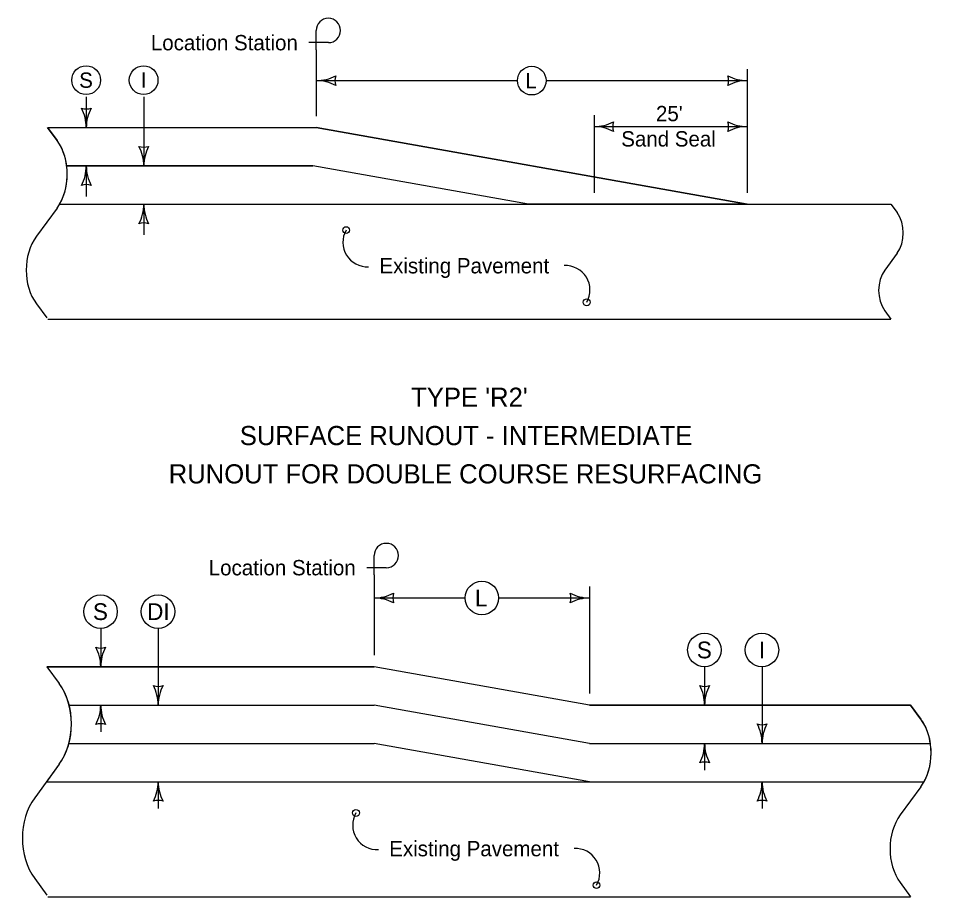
# Model space of a CAD drawing. Extents: x 10133 to 81668, y 2218 to 11018.
# Drawn here: x 20281 to 21238, y 3162 to 4079 of the extents above; entities that cross this region are included whole.
import ezdxf

# ---------------------------------------------------------------- set-up
doc = ezdxf.new("R2010")
doc.units = 0
for name, color, linetype in [('dsnNonPlotable', 7, 'Continuous'), ('dsnStdBlock', 7, 'Continuous'), ('dsnStdBlockNotModified', 7, 'Continuous'), ('dsnStdShading', 7, 'Continuous')]:
    doc.layers.add(name, color=color, linetype=linetype)

msp = doc.modelspace()

# ---------------------------------------------------------------- linework, layer by layer
at = {"layer": 'dsnNonPlotable'}
for p, q in [((20652.45, 3402.05), (20310.91, 3402.05)), ((20310.91, 3402.05), (20323.71, 3384.58)), ((20652.45, 3402.05), (20310.91, 3402.05)), ((20310.91, 3402.05), (20323.71, 3384.58)), ((20877.45, 3362.05), (20652.45, 3402.05)), ((20877.45, 3362.05), (20652.45, 3402.05)), ((21212.45, 3362.05), (20877.45, 3362.05)), ((21212.45, 3362.05), (20877.45, 3362.05)), ((21222.87, 3347.82), (21212.45, 3362.05)), ((21222.87, 3347.82), (21212.45, 3362.05)), ((20323.71, 3300.26), (20310.37, 3282.05)), ((20323.71, 3300.26), (20310.37, 3282.05)), ((20310.37, 3282.05), (20877.45, 3282.05)), ((20310.37, 3282.05), (20877.45, 3282.05)), ((20877.45, 3282.05), (21226.58, 3282.05)), ((20877.45, 3282.05), (21226.58, 3282.05))]:
    msp.add_line(p, q, dxfattribs=at)
for centre, major_axis, ratio, start_param, end_param in [((20292.82, 3342.42), (0, -59.62), 0.732667, 0.785328, 2.356194), ((20292.82, 3342.42), (0, -59.62), 0.732667, 0.785328, 2.356194), ((21197.28, 3312.05), (0, -50), 0.73263, 0.927302, 2.368135), ((21197.28, 3312.05), (0, -50), 0.73263, 0.927302, 2.368135)]:
    msp.add_ellipse(centre, major_axis=major_axis, ratio=ratio, start_param=start_param, end_param=end_param, dxfattribs=at)
at = {"layer": 'dsnStdBlock'}
for p, q in [((20592.01, 4045.8), (20592.01, 4066.12)), ((20592.01, 4045.8), (20592.01, 4066.12)), ((20604.71, 4053.42), (20584.39, 4053.42)), ((20604.71, 4053.42), (20584.39, 4053.42)), ((20592.01, 4045.8), (20592.01, 3976.8)), ((20592.01, 4045.8), (20592.01, 3976.8)), ((21042.01, 4025.8), (21042.01, 3896.8)), ((21042.01, 4025.8), (21042.01, 3896.8)), ((20592.01, 4013.8), (20802.02, 4013.8)), ((20592.01, 4013.8), (20802.02, 4013.8)), ((20832.02, 4013.8), (21042.01, 4013.8)), ((20832.02, 4013.8), (21042.01, 4013.8)), ((20352.01, 3996.8), (20352.01, 3964.8)), ((20352.01, 3996.8), (20352.01, 3964.8)), ((20412.01, 3996.8), (20412.01, 3924.8)), ((20412.01, 3996.8), (20412.01, 3924.8)), ((20882.01, 3977.8), (20882.01, 3896.8)), ((20882.01, 3977.8), (20882.01, 3896.8)), ((20311.65, 3964.8), (20321.45, 3951.42)), ((20311.65, 3964.8), (20321.45, 3951.42)), ((20312.01, 3964.8), (20592.01, 3964.8)), ((20312.01, 3964.8), (20592.01, 3964.8)), ((21042.01, 3884.8), (20592.01, 3964.8)), ((21042.01, 3884.8), (20592.01, 3964.8)), ((20882.01, 3965.8), (21042.01, 3965.8)), ((20882.01, 3965.8), (21042.01, 3965.8)), ((20331.62, 3924.8), (20588.49, 3924.8)), ((20331.62, 3924.8), (20588.49, 3924.8)), ((20352.01, 3924.8), (20352.01, 3892.8)), ((20352.01, 3924.8), (20352.01, 3892.8)), ((20813.49, 3884.8), (20588.49, 3924.8)), ((20813.49, 3884.8), (20588.49, 3924.8)), ((20324.46, 3884.8), (20813.49, 3884.8)), ((20324.46, 3884.8), (20813.49, 3884.8)), ((20412.01, 3884.8), (20412.01, 3852.8)), ((20412.01, 3884.8), (20412.01, 3852.8)), ((20813.49, 3884.8), (21042.01, 3884.8)), ((20813.49, 3884.8), (21042.01, 3884.8)), ((21042.01, 3884.8), (21192.01, 3884.8)), ((21042.01, 3884.8), (21192.01, 3884.8)), ((21192.01, 3884.8), (21198.45, 3876.02)), ((21192.01, 3884.8), (21198.45, 3876.02)), ((20321.45, 3880.7), (20300, 3851.42)), ((20321.45, 3880.7), (20300, 3851.42)), ((21198.45, 3833.59), (21185.58, 3816.02)), ((21198.45, 3833.59), (21185.58, 3816.02)), ((20300, 3780.7), (20310.73, 3766.06)), ((20300, 3780.7), (20310.73, 3766.06)), ((21185.58, 3773.59), (21192.01, 3764.8)), ((21185.58, 3773.59), (21192.01, 3764.8)), ((20312.01, 3764.8), (21192.01, 3764.8)), ((20312.01, 3764.8), (21192.01, 3764.8)), ((20652.45, 3497.81), (20652.45, 3518.13)), ((20652.45, 3497.81), (20652.45, 3518.13)), ((20665.15, 3505.43), (20644.83, 3505.43)), ((20665.15, 3505.43), (20644.83, 3505.43)), ((20652.45, 3497.81), (20652.45, 3414.05)), ((20652.45, 3497.81), (20652.45, 3414.05)), ((20877.45, 3485.81), (20877.45, 3374.05)), ((20877.45, 3485.81), (20877.45, 3374.05)), ((20652.45, 3473.81), (20747.45, 3473.81)), ((20652.45, 3473.81), (20747.45, 3473.81)), ((20782.45, 3473.81), (20877.45, 3473.81)), ((20782.45, 3473.81), (20877.45, 3473.81)), ((20367.08, 3442.05), (20367.08, 3402.05)), ((20367.08, 3442.05), (20367.08, 3402.05)), ((20427.08, 3442.05), (20427.08, 3362.05)), ((20427.08, 3442.05), (20427.08, 3362.05)), ((20310.91, 3402.05), (20652.45, 3402.05)), ((20310.91, 3402.05), (20652.45, 3402.05)), ((20310.91, 3402.04), (20323.71, 3384.59)), ((20310.91, 3402.04), (20323.71, 3384.59)), ((20877.45, 3362.05), (20652.45, 3402.05)), ((20877.45, 3362.05), (20652.45, 3402.05)), ((20997.45, 3402.05), (20997.45, 3362.05)), ((20997.45, 3402.05), (20997.45, 3362.05)), ((21057.45, 3402.05), (21057.45, 3322.05)), ((21057.45, 3402.05), (21057.45, 3322.05)), ((20334.07, 3362.05), (20652.45, 3362.05)), ((20334.07, 3362.05), (20652.45, 3362.05)), ((20367.08, 3362.05), (20367.08, 3334.05)), ((20367.08, 3362.05), (20367.08, 3334.05)), ((20877.45, 3322.05), (20652.45, 3362.05)), ((20877.45, 3322.05), (20652.45, 3362.05)), ((20877.45, 3362.05), (21212.45, 3362.05)), ((20877.45, 3362.05), (21212.45, 3362.05)), ((21212.45, 3362.05), (21223.17, 3347.4)), ((21212.45, 3362.05), (21223.17, 3347.4)), ((20333.88, 3322.05), (20652.45, 3322.05)), ((20333.88, 3322.05), (20652.45, 3322.05)), ((20877.45, 3282.05), (20652.45, 3322.05)), ((20877.45, 3282.05), (20652.45, 3322.05)), ((20877.45, 3322.05), (21233.17, 3322.05)), ((20877.45, 3322.05), (21233.17, 3322.05)), ((20997.45, 3322.05), (20997.45, 3294.05)), ((20997.45, 3322.05), (20997.45, 3294.05)), ((20323.71, 3300.26), (20298.13, 3265.34)), ((20323.71, 3300.26), (20298.13, 3265.34)), ((20310.37, 3282.05), (20877.45, 3282.05)), ((20310.37, 3282.05), (20877.45, 3282.05)), ((20427.08, 3282.05), (20427.08, 3254.05)), ((20427.08, 3282.05), (20427.08, 3254.05)), ((20877.45, 3282.05), (21226.58, 3282.05)), ((20877.45, 3282.05), (21226.58, 3282.05)), ((21057.45, 3282.05), (21057.45, 3254.05)), ((21057.45, 3282.05), (21057.45, 3254.05)), ((21223.17, 3276.69), (21201.73, 3247.4)), ((21223.17, 3276.69), (21201.73, 3247.4)), ((20298.13, 3181.01), (20310.91, 3163.55)), ((20298.13, 3181.01), (20310.91, 3163.55)), ((21201.73, 3176.69), (21212.45, 3162.05)), ((21201.73, 3176.69), (21212.45, 3162.05)), ((20312.01, 3162.05), (21212.45, 3162.05)), ((20312.01, 3162.05), (21212.45, 3162.05))]:
    msp.add_line(p, q, dxfattribs=at)
for centre, radius in [((20351.83, 4014.3), 15), ((20351.83, 4014.3), 15), ((20411.83, 4014.3), 15), ((20411.83, 4014.3), 15), ((20817.02, 4013.8), 15), ((20817.02, 4013.8), 15), ((20623.27, 3857.8), 3.56), ((20623.27, 3857.8), 3.56), ((20874.4, 3782.44), 3.56), ((20874.4, 3782.44), 3.56), ((20764.95, 3473.81), 17.5), ((20764.95, 3473.81), 17.5), ((20366.9, 3459.55), 17.5), ((20366.9, 3459.55), 17.5), ((20426.9, 3459.55), 17.5), ((20426.9, 3459.55), 17.5), ((20997.27, 3419.55), 17.5), ((20997.27, 3419.55), 17.5), ((21057.27, 3419.55), 17.5), ((21057.27, 3419.55), 17.5), ((20633.49, 3249.41), 3.56), ((20633.49, 3249.41), 3.56), ((20884.62, 3174.05), 3.56), ((20884.62, 3174.05), 3.56)]:
    msp.add_circle(centre, radius, dxfattribs=at)
for centre, radius, start, end in [((20604.71, 4066.12), 12.7, 270, 180), ((20604.71, 4066.12), 12.7, 270, 180), ((20592.01, 4056.98), 43.18, 270, 298.07249), ((20592.01, 4056.98), 43.18, 270, 298.07249), ((20628.22, 4013.8), 16.68, 162.26665, 197.73335), ((20628.22, 4013.8), 16.68, 162.26665, 197.73335), ((21005.81, 4013.8), 16.68, 342.26665, 17.73335), ((21042.01, 4056.98), 43.18, 241.92751, 270), ((21005.81, 4013.8), 16.68, 342.26665, 17.73335), ((21042.01, 4056.98), 43.18, 241.92751, 270), ((20592.01, 3970.62), 43.18, 61.92751, 90), ((20592.01, 3970.62), 43.18, 61.92751, 90), ((21042.01, 3970.62), 43.18, 90, 118.07249), ((21042.01, 3970.62), 43.18, 90, 118.07249), ((20352.01, 4001.01), 16.68, 252.26665, 287.73335), ((20308.83, 3964.8), 43.18, 360, 28.07249), ((20352.01, 4001.01), 16.68, 252.26665, 287.73335), ((20308.83, 3964.8), 43.18, 360, 28.07249), ((20395.19, 3964.8), 43.18, 151.92751, 180), ((20395.19, 3964.8), 43.18, 151.92751, 180), ((20882.01, 4008.98), 43.18, 270, 298.07249), ((20882.01, 4008.98), 43.18, 270, 298.07249), ((20918.22, 3965.8), 16.68, 162.26665, 197.73335), ((20918.22, 3965.8), 16.68, 162.26665, 197.73335), ((21005.81, 3965.8), 16.68, 342.26665, 17.73335), ((21042.01, 4008.98), 43.18, 241.92751, 270), ((21005.81, 3965.8), 16.68, 342.26665, 17.73335), ((21042.01, 4008.98), 43.18, 241.92751, 270), ((20882.01, 3922.62), 43.18, 61.92751, 90), ((20882.01, 3922.62), 43.18, 61.92751, 90), ((21042.01, 3922.62), 43.18, 90, 118.07249), ((21042.01, 3922.62), 43.18, 90, 118.07249), ((20412.01, 3961.01), 16.68, 252.26665, 287.73335), ((20368.83, 3924.8), 43.18, 360, 28.07249), ((20412.01, 3961.01), 16.68, 252.26665, 287.73335), ((20368.83, 3924.8), 43.18, 360, 28.07249), ((20412.01, 3961.01), 16.68, 252.26665, 287.73335), ((20368.83, 3924.8), 43.18, 360, 28.07249), ((20412.01, 3961.01), 16.68, 252.26665, 287.73335), ((20368.83, 3924.8), 43.18, 360, 28.07249), ((20455.19, 3924.8), 43.18, 151.92751, 180), ((20455.19, 3924.8), 43.18, 151.92751, 180), ((20455.19, 3924.8), 43.18, 151.92751, 180), ((20455.19, 3924.8), 43.18, 151.92751, 180), ((20308.83, 3924.8), 43.18, 331.92751, 360), ((20308.83, 3924.8), 43.18, 331.92751, 360), ((20395.19, 3924.8), 43.18, 180, 208.07249), ((20395.19, 3924.8), 43.18, 180, 208.07249), ((20352.01, 3888.6), 16.68, 72.26665, 107.73335), ((20352.01, 3888.6), 16.68, 72.26665, 107.73335), ((20368.83, 3884.8), 43.18, 331.92751, 360), ((20368.83, 3884.8), 43.18, 331.92751, 360), ((20455.19, 3884.8), 43.18, 180, 208.07249), ((20455.19, 3884.8), 43.18, 180, 208.07249), ((20412.01, 3848.6), 16.68, 72.26665, 107.73335), ((20412.01, 3848.6), 16.68, 72.26665, 107.73335), ((20645.42, 3845.05), 25.56, 150.06834, 272.84357), ((20645.42, 3845.05), 25.56, 150.06834, 272.84357), ((20852.25, 3795.2), 25.56, 330.06834, 92.84357), ((20852.25, 3795.2), 25.56, 330.06834, 92.84357), ((20665.15, 3518.13), 12.7, 270, 180), ((20665.15, 3518.13), 12.7, 270, 180), ((20652.45, 3516.99), 43.18, 270, 298.07249), ((20652.45, 3516.99), 43.18, 270, 298.07249), ((20652.45, 3430.63), 43.18, 61.92751, 90), ((20652.45, 3430.63), 43.18, 61.92751, 90), ((20688.66, 3473.81), 16.68, 162.26665, 197.73335), ((20688.66, 3473.81), 16.68, 162.26665, 197.73335), ((20841.24, 3473.81), 16.68, 342.26665, 17.73335), ((20877.45, 3516.99), 43.18, 241.92751, 270), ((20841.24, 3473.81), 16.68, 342.26665, 17.73335), ((20877.45, 3516.99), 43.18, 241.92751, 270), ((20877.45, 3430.63), 43.18, 90, 118.07249), ((20877.45, 3430.63), 43.18, 90, 118.07249), ((20367.08, 3438.25), 16.68, 252.26665, 287.73335), ((20323.9, 3402.05), 43.18, 360, 28.07249), ((20367.08, 3438.25), 16.68, 252.26665, 287.73335), ((20323.9, 3402.05), 43.18, 360, 28.07249), ((20410.26, 3402.05), 43.18, 151.92751, 180), ((20410.26, 3402.05), 43.18, 151.92751, 180), ((20427.08, 3398.25), 16.68, 252.26665, 287.73335), ((20383.9, 3362.05), 43.18, 360, 28.07249), ((20427.08, 3398.25), 16.68, 252.26665, 287.73335), ((20383.9, 3362.05), 43.18, 360, 28.07249), ((20470.26, 3362.05), 43.18, 151.92751, 180), ((20470.26, 3362.05), 43.18, 151.92751, 180), ((20997.45, 3398.25), 16.68, 252.26665, 287.73335), ((20954.27, 3362.05), 43.18, 360, 28.07249), ((20997.45, 3398.25), 16.68, 252.26665, 287.73335), ((20954.27, 3362.05), 43.18, 360, 28.07249), ((21040.63, 3362.05), 43.18, 151.92751, 180), ((21040.63, 3362.05), 43.18, 151.92751, 180), ((20323.9, 3362.05), 43.18, 331.92751, 360), ((20323.9, 3362.05), 43.18, 331.92751, 360), ((20410.26, 3362.05), 43.18, 180, 208.07249), ((20410.26, 3362.05), 43.18, 180, 208.07249), ((20367.08, 3325.84), 16.68, 72.26665, 107.73335), ((20367.08, 3325.84), 16.68, 72.26665, 107.73335), ((21057.45, 3358.25), 16.68, 252.26665, 287.73335), ((21014.27, 3322.05), 43.18, 360, 28.07249), ((21057.45, 3358.25), 16.68, 252.26665, 287.73335), ((21014.27, 3322.05), 43.18, 360, 28.07249), ((21100.63, 3322.05), 43.18, 151.92751, 180), ((21100.63, 3322.05), 43.18, 151.92751, 180), ((20954.27, 3322.05), 43.18, 331.92751, 360), ((20954.27, 3322.05), 43.18, 331.92751, 360), ((21040.63, 3322.05), 43.18, 180, 208.07249), ((21040.63, 3322.05), 43.18, 180, 208.07249), ((20997.45, 3285.84), 16.68, 72.26665, 107.73335), ((20997.45, 3285.84), 16.68, 72.26665, 107.73335), ((20383.9, 3282.05), 43.18, 331.92751, 360), ((20383.9, 3282.05), 43.18, 331.92751, 360), ((20470.26, 3282.05), 43.18, 180, 208.07249), ((20470.26, 3282.05), 43.18, 180, 208.07249), ((21014.27, 3282.05), 43.18, 331.92751, 360), ((21014.27, 3282.05), 43.18, 331.92751, 360), ((21100.63, 3282.05), 43.18, 180, 208.07249), ((21100.63, 3282.05), 43.18, 180, 208.07249), ((20427.08, 3245.84), 16.68, 72.26665, 107.73335), ((20427.08, 3245.84), 16.68, 72.26665, 107.73335), ((21057.45, 3245.84), 16.68, 72.26665, 107.73335), ((21057.45, 3245.84), 16.68, 72.26665, 107.73335), ((20655.64, 3236.66), 25.56, 150.06834, 272.84357), ((20655.64, 3236.66), 25.56, 150.06834, 272.84357), ((20862.47, 3186.81), 25.56, 330.06834, 92.84357), ((20862.47, 3186.81), 25.56, 330.06834, 92.84357)]:
    msp.add_arc(centre, radius, start, end, dxfattribs=at)
for centre, major_axis, ratio in [((20295.55, 3916.06), (0, -50), 0.732645), ((20295.55, 3916.06), (0, -50), 0.732645), ((21182.91, 3854.8), (0, -30), 0.732645), ((21182.91, 3854.8), (0, -30), 0.732645), ((20325.9, 3816.06), (0, 50), 0.732645), ((20325.9, 3816.06), (0, 50), 0.732645), ((21201.12, 3794.8), (0, 30), 0.732645), ((21201.12, 3794.8), (0, 30), 0.732645), ((20292.82, 3342.42), (0, -59.62), 0.732667), ((20292.82, 3342.42), (0, -59.62), 0.732667), ((21197.28, 3312.05), (0, -50), 0.73263), ((21197.28, 3312.05), (0, -50), 0.73263), ((20329.01, 3223.18), (0, 59.62), 0.732667), ((20329.01, 3223.18), (0, 59.62), 0.732667), ((21227.62, 3212.05), (0, 50), 0.73263), ((21227.62, 3212.05), (0, 50), 0.73263)]:
    msp.add_ellipse(centre, major_axis=major_axis, ratio=ratio, start_param=0.785398, end_param=2.356194, dxfattribs=at)
at = {"layer": 'dsnStdShading'}
for p, q in [((20321.45, 3951.42), (20311.65, 3964.8)), ((20321.45, 3951.42), (20311.65, 3964.8)), ((20312.01, 3964.8), (20592.01, 3964.8)), ((20312.01, 3964.8), (20592.01, 3964.8)), ((20592.01, 3964.8), (21042.01, 3884.8)), ((20592.01, 3964.8), (21042.01, 3884.8)), ((20588.49, 3924.8), (20331.62, 3924.8)), ((20588.49, 3924.8), (20331.62, 3924.8)), ((20588.49, 3924.8), (20331.62, 3924.8)), ((20588.49, 3924.8), (20331.62, 3924.8)), ((20813.49, 3884.8), (20588.49, 3924.8)), ((20813.49, 3884.8), (20588.49, 3924.8)), ((20813.49, 3884.8), (20588.49, 3924.8)), ((20813.49, 3884.8), (20588.49, 3924.8)), ((20324.14, 3884.8), (20813.49, 3884.8)), ((20324.14, 3884.8), (20813.49, 3884.8)), ((21042.01, 3884.8), (20813.49, 3884.8)), ((21042.01, 3884.8), (20813.49, 3884.8))]:
    msp.add_line(p, q, dxfattribs=at)
for start_param, end_param in [(1.746484, 2.356194), (1.746484, 2.356194), (0.89539, 1.746484), (0.89539, 1.746484)]:
    msp.add_ellipse((20295.55, 3916.06), major_axis=(0, -50), ratio=0.732645, start_param=start_param, end_param=end_param, dxfattribs=at)

# ---------------------------------------------------------------- texts
at = {"layer": 'dsnStdBlockNotModified'}
for s, height, p in [('Location Station', 16, (20419.39, 4045.42)), ('Location Station', 16, (20419.39, 4045.42)), ('S', 16, (20344.59, 4006.3)), ('S', 16, (20344.59, 4006.3)), ('I', 16, (20408.97, 4006.3)), ('I', 16, (20408.97, 4006.3)), ('L', 16, (20810.38, 4005.8)), ('L', 16, (20810.38, 4005.8)), ("25'", 16, (20946.68, 3971.42)), ("25'", 16, (20946.68, 3971.42)), ('Sand Seal', 16, (20910.43, 3945.02)), ('Sand Seal', 16, (20910.43, 3945.02)), ('Existing Pavement', 16, (20658.02, 3812.57)), ('Existing Pavement', 16, (20658.02, 3812.57)), ("TYPE 'R2'", 20, (20691.11, 3673.35)), ("TYPE 'R2'", 20, (20691.11, 3673.35)), ('SURFACE RUNOUT - INTERMEDIATE', 20, (20512.23, 3633.35)), ('SURFACE RUNOUT - INTERMEDIATE', 20, (20512.23, 3633.35)), ('RUNOUT FOR DOUBLE COURSE RESURFACING', 20, (20438.06, 3593.35)), ('RUNOUT FOR DOUBLE COURSE RESURFACING', 20, (20438.06, 3593.35)), ('Location Station', 16, (20479.83, 3497.43)), ('Location Station', 16, (20479.83, 3497.43)), ('L', 17.5, (20757.69, 3465.06)), ('L', 17.5, (20757.69, 3465.06)), ('S', 17.5, (20358.98, 3450.8)), ('S', 17.5, (20358.98, 3450.8)), ('DI', 17.5, (20415.57, 3450.8)), ('DI', 17.5, (20415.57, 3450.8)), ('S', 17.5, (20989.35, 3410.8)), ('S', 17.5, (20989.35, 3410.8)), ('I', 17.5, (21054.13, 3410.8)), ('I', 17.5, (21054.13, 3410.8)), ('Existing Pavement', 16, (20668.24, 3204.18)), ('Existing Pavement', 16, (20668.24, 3204.18))]:
    msp.add_text(s, height=height, dxfattribs=at).set_placement(p)

doc.saveas('drawing.dxf')
